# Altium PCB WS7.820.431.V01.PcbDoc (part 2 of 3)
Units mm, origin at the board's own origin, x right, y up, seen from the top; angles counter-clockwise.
Board outline 461 x 63.5 mm, 4 copper layers (Top Layer, Mid-Layer1, Mid-Layer 2, Bottom Layer); 379 components, 227 nets, 1092 pads, 3835 vias.
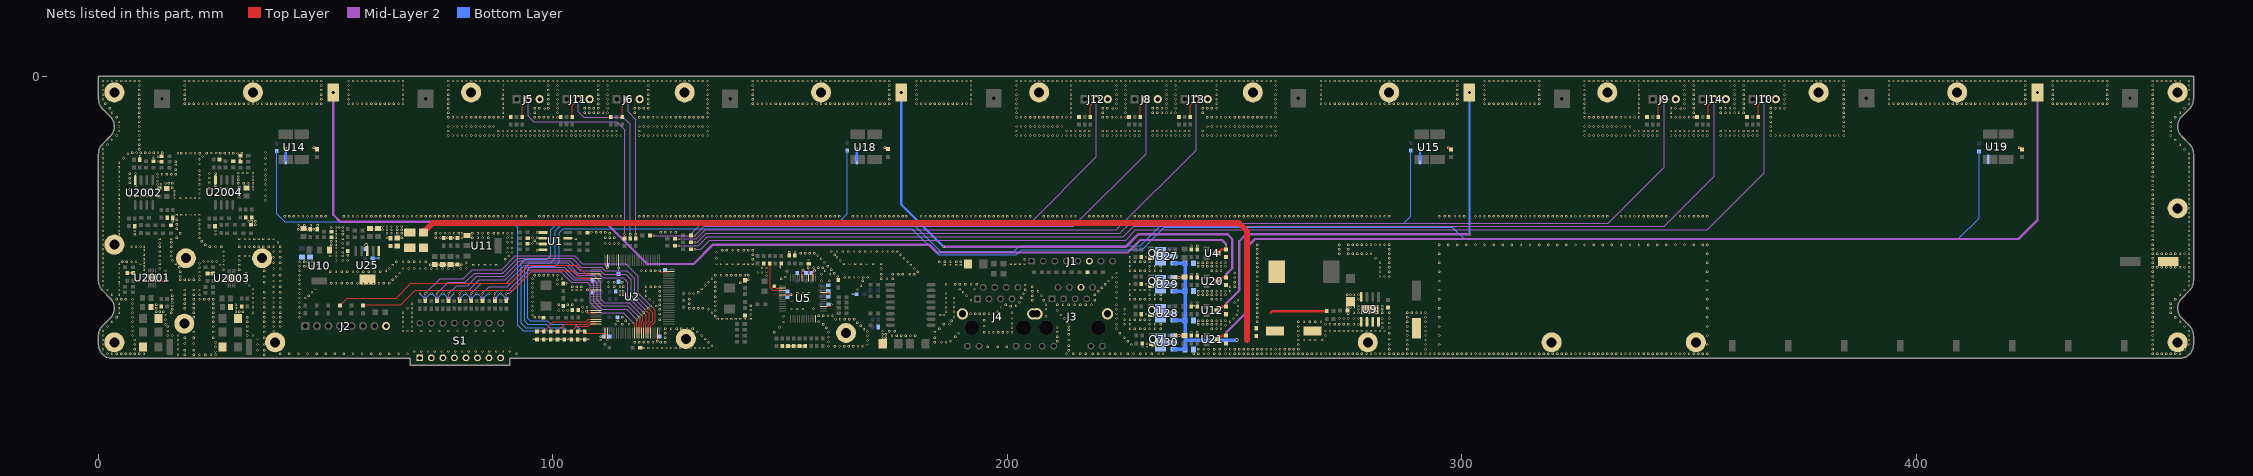
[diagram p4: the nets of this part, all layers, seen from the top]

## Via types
v1: diameter 0.508, hole 0.305, Top Layer to Bottom Layer, tented both sides, 3797 vias
v2: diameter 0.66, hole 0.406, Top Layer to Bottom Layer, tented both sides, 20 vias
v3: diameter 0.6, hole 0.305, Top Layer to Bottom Layer, tented both sides, 10 vias
v4: diameter 0.813, hole 0.508, Top Layer to Bottom Layer, tented both sides, 7 vias
v5: diameter 0.508, hole 0.3, Top Layer to Bottom Layer, tented both sides, 1 vias

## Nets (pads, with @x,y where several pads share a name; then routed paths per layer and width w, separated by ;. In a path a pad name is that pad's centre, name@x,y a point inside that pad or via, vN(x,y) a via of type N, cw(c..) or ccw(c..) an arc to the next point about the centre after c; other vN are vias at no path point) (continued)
+5V_13: FB16.2 R104.2 U29.1 | length 2.6
  Top Layer w0.381: R104.2@237.237,-44.209 R104.2@237.287,-44.159
  Top Layer w0.508: R104.2@237.287,-44.159 237.349,-44.221 237.721,-44.221 v2(237.75,-44.25) 237.779,-44.221 238.827,-44.221 FB16.2@238.888,-44.159
  Bottom Layer w0.508: U29.1@236.925,-44.159 236.995,-44.229 237.729,-44.229 v2(237.75,-44.25)
+5V_14: FB17.2 R105.2 U30.1 | length 2.9
  Top Layer w0.508: R105.2@237.244,-57.05 237.659,-57.05 237.709,-57 v2(237.75,-57) 237.761,-56.989 238.926,-56.989 FB17.2@238.937,-56.978
  Bottom Layer w0.508: U30.1@236.633,-57.035 236.65,-57.018 237.732,-57.018 v2(237.75,-57)
+5V_GS1: C142.2 TP17.1 U4.3 | length 235.3
  Top Layer w0.508: U4.3@246.238,-38.918 246.388,-38.918 246.634,-38.672 246.634,-38.522 247.088,-38.068 C142.2@248.104,-38.068 v1(248.104,-37.445)
  Mid-Layer 2 w0.508: TP17.1@51.662,-3.524 51.662,-30.412 53.25,-32 111.5,-32 120.75,-41.25 131,-41.25 135.25,-37 182.75,-37 184.5,-38.75 226.5,-38.75 229.25,-36 247.25,-36 248.104,-36.854 v1(248.104,-37.445)
+5V_GS2: C114.2 TP18.1 U20.3 | length 114.2
  Top Layer w0.508: U20.3@246.238,-45.05 246.388,-45.05 246.634,-44.804 246.634,-44.654 247.038,-44.25 C114.2@248.104,-44.25 ; C114.2@248.104,-44.2 v1(248.104,-43.577)
  Mid-Layer 2 w0.508: v1(186,-37.5) 226,-37.5 228.75,-34.75 248.5,-34.75 249.5,-35.75 249.5,-42.181 v1(248.104,-43.577)
  Bottom Layer w0.508: TP18.1@176.662,-3.524 176.662,-28.162 v1(186,-37.5)
+5V_GS3: C52.2 TP19.1 U12.3 | length 100.4
  Top Layer w0.508: U12.3@246.238,-51.465 246.388,-51.465 246.634,-51.219 246.634,-51.069 247.038,-50.665 C52.2@248.104,-50.665 ; C52.2@248.104,-50.615 v1(248.104,-49.992)
  Mid-Layer 2 w0.508: v1(248.104,-49.992) 251,-47.096 251,-36.251 252.501,-34.75 v1(301.662,-34.75)
  Bottom Layer w0.508: v1(301.662,-34.75) TP19.1@301.662,-3.524
+5V_GS4: C121.2 TP20.1 U21.3 | length 227.5
  Top Layer w0.508: U21.3@246.238,-57.878 246.388,-57.878 247.238,-57.028 C121.2@248.104,-57.028
  Mid-Layer 2 w0.508: v1(248.104,-56.405) 252.5,-52.009 252.5,-37.75 254.5,-35.75 422.5,-35.75 426.662,-31.588 TP20.1@426.662,-3.524
+6.9V: C12.2 C72.1 C132.2 C133.2 C134.2 C135.2 FB7.1 L4.2 R80.2 U27.3 U28.3 U29.3 U30.3 | length 259.9
  Top Layer w0.508: 257.92,-52.063 258.333,-51.65 R80.2@270.25,-51.65
  Top Layer w1.27: FB7.1@71.5,-34.3 71.6,-34.3 71.865,-34.035 71.865,-33.935 73.55,-32.25 250.965,-32.25 252.75,-34.035 252.75,-58
  Bottom Layer w0.762: U28.3@236.633,-53.622 236.649,-53.639 239.084,-53.639 C134.2@239.101,-53.655 ; U29.3@236.633,-47.207 236.649,-47.223 239.084,-47.223 C133.2@239.101,-47.24 ; U27.3@236.633,-41.075 236.649,-41.091 239.084,-41.091 C132.2@239.101,-41.108 C133.2@239.101,-47.24 ; U30.3@236.726,-59.942 U30.3@236.633,-60.035 236.665,-60.067 238.932,-60.067 239.08,-59.919 C135.2@239.08,-59.917 ; C135.2@239.055,-59.942 C135.2@239.08,-59.917 ; C135.2@239.207,-60.044 C135.2@239.08,-59.917 ; v4(250.5,-58) 239.101,-58 ; C135.2@239.08,-59.917 239.101,-59.896 239.101,-58 ; 239.101,-58 C134.2@239.101,-53.655 ; C134.2@239.101,-53.655 C133.2@239.101,-47.24
+6.9VIN: C128.2 C181.2 C183.2 FB7.2 R231.2 U25.1 | length 1.4
  Bottom Layer w0.381: R231.2@60.35,-40 v1(61.75,-40)
ACTLED: R45.2 U5.27 | length 8.3
  Top Layer w0.254: R45.2@147.782,-41.164 147.782,-46.472 148.376,-47.066 U5.27@150.529,-47.066
BD_TEMP1: J5.2 R24.2 R109.2 | length 54.6
  Top Layer w0.254: R24.2@93.25,-8.9 93.25,-6.29 J5.2@94.54,-5 ; R109.2@115.75,-35.65 v1(115.75,-34.75)
  Mid-Layer 2 w0.254: J5.2@94.54,-5 94.54,-8.79 95.75,-10 114.027,-10 115.75,-11.723 v1(115.75,-34.75)
BD_TEMP2: J11.2 R20.2 R110.2 | length 45
  Top Layer w0.254: R20.2@104.25,-8.9 104.25,-6.29 J11.2@105.54,-5 ; R110.2@117,-35.65 v1(117,-34.75)
  Mid-Layer 2 w0.254: J11.2@105.54,-5 105.54,-7.79 106.75,-9 115.5,-9 117,-10.5 v1(117,-34.75)
BD_TEMP3: J6.2 R21.2 R111.2 | length 35.8
  Top Layer w0.254: R21.2@115.25,-8.9 115.25,-6.29 J6.2@116.54,-5 ; R111.2@118.25,-35.65 v1(118.25,-34.75)
  Mid-Layer 2 w0.254: J6.2@116.54,-5 116.54,-7.79 118.25,-9.5 v1(118.25,-34.75)
BD_TEMP4: J12.2 R22.2 R112.2 | length 122.5
  Top Layer w0.254: R112.2@121.35,-35 v1(122.25,-35) ; R22.2@218.25,-8.9 218.25,-6.29 J12.2@219.54,-5
  Mid-Layer 2 w0.254: v1(122.25,-35) 130,-35 132.75,-32.25 205,-32.25 219.54,-17.71 J12.2@219.54,-5
BD_TEMP5: J8.2 R23.2 R113.2 | length 124.1
  Top Layer w0.254: R113.2@130.35,-35 v1(131.25,-35) ; R23.2@229.25,-8.9 229.25,-6.29 J8.2@230.54,-5
  Mid-Layer 2 w0.254: v1(131.25,-35) 133.25,-33 214.5,-33 230.54,-16.96 J8.2@230.54,-5
BD_TEMP6: J13.2 R62.2 R114.2 | length 138.4
  Top Layer w0.254: R114.2@126.85,-35.75 v1(127.75,-35.75) ; R62.2@240.25,-8.9 240.25,-6.29 J13.2@241.54,-5
  Mid-Layer 2 w0.254: v1(127.75,-35.75) 131.5,-35.75 133.5,-33.75 224,-33.75 241.54,-16.21 J13.2@241.54,-5
BD_TEMP7: J9.2 R70.2 R115.2 | length 240.4
  Top Layer w0.254: R115.2@130.35,-36.5 v1(131.25,-36.5) ; R70.2@343.25,-8.9 343.25,-6.29 J9.2@344.54,-5
  Mid-Layer 2 w0.254: v1(131.25,-36.5) 131.75,-36.5 133.75,-34.5 224.75,-34.5 227,-32.25 332.25,-32.25 344.54,-19.96 J9.2@344.54,-5
BD_TEMP8: J14.2 R79.2 R116.2 | length 256.4
  Top Layer w0.254: R116.2@126.85,-37.25 v1(127.75,-37.25) ; R79.2@354.25,-8.9 354.25,-6.29 J14.2@355.54,-5
  Mid-Layer 2 w0.254: v1(127.75,-37.25) 132,-37.25 134,-35.25 225.5,-35.25 227.75,-33 344.5,-33 355.54,-21.96 J14.2@355.54,-5
BD_TEMP9: J10.2 R81.2 R117.2 | length 263.8
  Top Layer w0.254: R117.2@130.35,-38 v1(131.25,-38) ; R81.2@365.25,-8.9 365.25,-6.29 J10.2@366.54,-5
  Mid-Layer 2 w0.254: v1(131.25,-38) 132.5,-38 134.5,-36 226,-36 228.25,-33.75 354,-33.75 366.54,-21.21 J10.2@366.54,-5
BOOT0: R10.2 U2.94 | length 3
  Top Layer w0.254: v1(114.468,-42.117) U2.94@114.468,-40.455
  Bottom Layer w0.254: R10.2@114.468,-43.438 v1(114.468,-42.117)
COMM_LED: R32.2 U2.5 | length 55.1
  Top Layer w0.254: R32.2@58.216,-50.404 58.37,-50.25 66.5,-50.25 69.75,-47 91.25,-47 95.5,-42.75 104.5,-42.75 106.205,-44.455 U2.5@109.468,-44.455
CURR_LED: R30.2 U2.3 | length 60.9
  Top Layer w0.254: R30.2@53.136,-50.404 53.136,-50.354 53.409,-50.081 53.459,-50.081 54.79,-48.75 65.5,-48.75 68.75,-45.5 90.75,-45.5 94.75,-41.5 105.252,-41.5 107.206,-43.455 U2.3@109.468,-43.455
DUPLED: TP1.1 U5.26 | length 2
  Top Layer w0.254: TP1.1@148.679,-46.149 149.096,-46.566 U5.26@150.529,-46.566
GND: C1.1 C2.1 C3.1 C4.1 C5.1 C6.1 C7.1 C8.1 C9.1 C10.2 C11.2 C12.1 C15.1 C18.2 C19.2 C22.1 C23.1 C24.1 C25.1 C26.1 C27.1 C28.1 C29.1 C30.1 C31.1 C32.1 C33.1 C34.1 C35.1 C36.1 C37.1 C38.1 C39.1 C40.1 C41.1 C42.1 C43.1 C52.1 C61.1 C64.2 C65.1 C66.1 C67.1 C68.1 C69.1 C70.1 C71.2 C72.2 C73.1 C74.1 C75.2 C76.1 C77.1 C78.1 C79.1 C80.1 C82.1 C83.1 C84.1 C85.1 C86.1 C87.2 C88.1 C89.1 C90.2 C91.2 C92.1 C93.1 C94.1 C95.1 C98.2 C99.2 C100.1 C101.1 C102.2 C103.1 C104.1 C105.1 C106.1 C107.2 C108.2 C109.2 C110.2 C114.1 C121.1 C128.1 C129.1 C132.1 C133.1 C134.1 C135.1 C141.1 C142.1 C181.1 C182.1 C183.1 C185.1 C2001.1 C2002.2 C2005.2 C2006.2 C2009.1 C2010.1 C2011.1 C2012.1 C2013.1 C2014.1 C2015.1 C2016.2 C2019.2 C2020.2 C2023.1 C2024.1 C2025.1 C2026.1 C2027.1 C2028.1 D1.1 D2.2 D3.2 D4.2 D5.2 D6.2 D7.2 D8.2 D9.2 J1.6 J2.8 J3.6 J3.13 J3.14 J4.13 J4.14 J5.3 J6.3 J8.3 J9.3 J10.3 J11.3 J12.3 J13.3 J14.3 pad.@3.5,-3.5 pad.@3.5,-37 pad.@3.5,-58.5 pad.@18.88,-54.4 pad.@19.25,-40 pad.@34,-3.5 pad.@36,-40 pad.@38.88,-58.5 pad.@82,-3.5 pad.@129,-3.5 pad.@129.25,-57.75 pad.@159,-3.5 pad.@164.5,-56.443 pad.@207,-3.5 pad.@254,-3.5 pad.@279.31,-58.5 pad.@284,-3.5 pad.@319.75,-58.5 pad.@332,-3.5 pad.@351.5,-58.5 pad.@378.5,-3.5 pad.@409,-3.5 pad.@457.5,-3.5 pad.@457.5,-29 pad.@457.5,-58.5 Q1.2 Q5.2 Q6.2 Q7.2 R8.1 R10.1 R15.1 R52.1 R55.1 R56.1 R57.1 R58.1 R59.1 R60.1 R82.2 R86.1 R103.1 R162.1 R165.1 R169.2 R184.1 R2002.2 R2009.1 R2010.1 R2011.1 R2016.1 R2018.1 R2021.1 R2027.1 R2031.1 R2032.1 R2033.1 R2037.1 S1.1 S1.2 S1.3 S1.4 S1.5 S1.6 S1.7 S1.8 U1.1 U1.2 U1.3 U1.4 U1.7 U2.10 U2.19 U2.20 U2.27 U2.49 U2.74 U2.99 U5.3 U5.9 U5.14 U5.16 U5.19 U5.29 U5.48 U9.4 U9.5 U9.6 U9.7 U9.8 U9.9 U10.1 U11.1 U14.4 U15.4 U18.4 U19.4 U25.3 U25.6 U27.2 U27.4 U28.2 U28.4 U29.2 U29.4 U30.2 U30.4 U2001.5 U2001.17 U2002.4 U2003.5 U2003.17 U2004.4 | length 62.5
  Top Layer w0.254: U2001.17@12.54,-45.09 U2001.5@13.39,-45.09 ; U2003.17@30.025,-45.15 U2003.5@30.875,-45.15 ; v1(107.583,-46.955) U2.10@109.468,-46.955 ; U2.20@109.468,-51.955 107.705,-51.955 v1(107.444,-51.693) 107.682,-51.455 U2.19@109.468,-51.455 ; U2.27@111.968,-56.455 111.968,-57.844 v1(112.013,-57.888) ; v1(111.968,-42.117) U2.99@111.968,-40.455 ; v1@122.968,-58.267 U2.49@122.968,-56.455 ; v1(123.5,-42.75) 123.569,-42.75 123.774,-42.955 U2.74@125.468,-42.955 ; U5.29@150.529,-48.066 152.35,-48.066 v3(152.362,-48.054) ; U5.19@154.779,-44.316 154.779,-42.97 v3(155.029,-42.72) ; U5.16@156.279,-44.316 156.279,-42.519 ; U5.14@157.279,-44.316 157.279,-43.137 157.696,-42.72 v3(157.569,-42.72) ; U5.3@159.529,-50.566 160.983,-50.566 161.303,-50.245 v1(161.303,-50.195) ; U5.9@159.529,-47.566 160.772,-47.566 v1(160.935,-47.729)
  Top Layer w0.305: U2001.5@13.39,-45.09 14.452,-45.09 14.537,-45.006
  Top Layer w0.508: C2001.1@6.33,-43.262 C2002.2@7.634,-43.262 ; C2015.1@23.992,-43.333 v1(24.697,-43.333) C2016.2@25.296,-43.333 ; v1(47.369,-15.716) 47.651,-15.716 C88.1@47.995,-16.06 ; v1(173.02,-15.716) 173.302,-15.716 C100.1@173.646,-16.06 ; v1(296.972,-15.716) 297.254,-15.716 C89.1@297.598,-16.06 ; v1(422.624,-15.716) 422.906,-15.716 C101.1@423.25,-16.06
  Bottom Layer w0.254: v1(70.75,-47.75) 70.75,-47.766 71.809,-48.825 D4.2@71.909,-48.825 72.009,-48.825 73.036,-47.799 73.201,-47.799 v1(73.25,-47.75) 73.299,-47.799 73.394,-47.799 74.42,-48.825 D2.2@74.52,-48.825 74.62,-48.825 75.695,-47.75 v1(75.75,-47.75) 75.799,-47.799 75.934,-47.799 76.96,-48.825 D3.2@77.06,-48.825 77.16,-48.825 78.235,-47.75 v1(78.25,-47.75) ; D6.2@79.461,-48.825 79.561,-48.825 80.587,-47.799 80.701,-47.799 v1(80.75,-47.75) 80.799,-47.799 80.875,-47.799 81.901,-48.825 D5.2@82.001,-48.825 82.101,-48.825 83.127,-47.799 83.201,-47.799 v1(83.25,-47.75) 83.3,-47.75 84.4,-48.85 D8.2@84.5,-48.85 84.6,-48.85 85.651,-47.799 85.951,-47.799 v1(86,-47.75) ; D9.2@87.25,-48.85 87.35,-48.85 88.45,-47.75 v1(88.5,-47.75) 88.55,-47.75 89.65,-48.85 D7.2@89.75,-48.85
  Bottom Layer w0.508: U14.4@41.183,-18.339 v1(41.183,-15.741) ; U18.4@166.834,-18.339 v1(166.834,-15.741) ; U15.4@290.786,-18.339 v1(290.786,-15.741)
  other v1: 17.5,-61.25 19,-61.25 21,-61.25 22.25,-61.25 23.5,-61.25 24.75,-61.25 25.75,-61.25 36.5,-61.25 2,-61 3,-61 4,-61 5,-61 6,-61 7,-61 8,-61 9,-61 10,-61 40,-61 42,-61 44,-61 46,-61 48,-61 50,-61 52,-61 54,-61 56,-61 58,-61 60,-61 62,-61 64,-61 66,-61 68,-61 92,-61 213,-61 214.5,-61 216,-61 217.25,-61 218.75,-61 220,-61 221.25,-61 222.5,-61 223.75,-61 225,-61 226.5,-61 227.75,-61 229.25,-61 230.5,-61 231.75,-61 233.25,-61 234.25,-61 241,-61 242,-61 243.25,-61 244.25,-61 245.5,-61 246.75,-61 248,-61 249,-61 250,-61 251,-61 252,-61 253,-61 254,-61 255,-61 256,-61 257,-61 258,-61 259,-61 260,-61 261,-61 262,-61 263,-61 264,-61 265,-61 266,-61 267,-61 268,-61 269,-61 269,-61 270,-61 271,-61 272,-61 273,-61 274,-61 275,-61 276,-61 277,-61 278,-61 279,-61 280,-61 281,-61 282,-61 283,-61 284,-61 285,-61 286,-61 287,-61 288,-61 289,-61 290,-61 291,-61 292,-61 293,-61 294,-61 295,-61 296,-61 297,-61 298,-61 299,-61 300,-61 301,-61 302,-61 303,-61 304,-61 305,-61 306,-61 307,-61 308,-61 309,-61 310,-61 311,-61 312,-61 313,-61 314,-61 315,-61 316,-61 317,-61 318,-61 319,-61 320,-61 321,-61 322,-61 323,-61 324,-61 325,-61 326,-61 327,-61 328,-61 329,-61 330,-61 331,-61 332,-61 333,-61 334,-61 335,-61 336,-61 337,-61 338,-61 339,-61 340,-61 341,-61 342,-61 343,-61 344,-61 345,-61 346,-61 347,-61 348,-61 349,-61 350,-61 351,-61 352,-61 353,-61 354,-61 354,-61 354,-61 452,-61 453,-61 454,-61 455,-61 456,-61 457,-61 458,-61 25.75,-60.5 69.5,-60.5 71,-60.5 72.5,-60.5 74,-60.5 75.5,-60.5 77,-60.5 78.5,-60.5 80,-60.5 81.5,-60.5 83,-60.5 84.5,-60.5 86,-60.5 87.5,-60.5 89,-60.5 90.5,-60.5 19,-60.25 21,-60.25 35,-60.25 36.5,-60.25 213.5,-60.25 1,-60 8,-60 17.5,-60 242,-60 243.25,-60 244.25,-60 245.5,-60 246.75,-60 248,-60 249,-60 250,-60 251,-60 252,-60 253,-60 254,-60 254,-60 255,-60 256,-60 257,-60 258,-60 259,-60 260,-60 261,-60 262,-60 263,-60 264,-60 284,-60 288,-60 292,-60 452,-60 459,-60 120,-59.75 121,-59.75 122,-59.75 123,-59.75 124,-59.75 125,-59.75 126,-59.75 127,-59.75 128,-59.75 130.25,-59.75 131.25,-59.75 132.25,-59.75 133.25,-59.75 134.25,-59.75 234.25,-59.75 229.726,-59.55 230.726,-59.55 231.945,-59.55 25.75,-59.5 233,-59.5 195.691,-59.484 197.85,-59.484 199.882,-59.484 162.04,-59.376 163.056,-59.376 164.072,-59.376 165.088,-59.376 166.104,-59.376 167.12,-59.376 168.136,-59.376 151.177,-59.357 152.447,-59.357 153.717,-59.357 154.987,-59.357 160.643,-59.364 135,-59.25 213.5,-59.25 169.227,-59.11 1,-59 8,-59 17.5,-59 35,-59 36.5,-59 227.25,-59 264,-59 284,-59 288,-59 292,-59 295,-59 354,-59 452,-59 460,-59 230.726,-58.8 19,-58.75 21,-58.75 25.75,-58.5 118,-58.5 119,-58.5 120,-58.5 121,-58.5 122,-58.5 123.75,-58.5 124.75,-58.5 134.25,-58.5 184,-58.5 185.5,-58.5 186.5,-58.5 160.643,-58.348 122.938,-58.297 187.5,-58.25 211,-58.25 226.5,-58.25 169.227,-58.094 1,-58 8,-58 17.5,-58 110.5,-58 213.5,-58 264,-58 265.25,-58 266.5,-58 267.75,-58 269.25,-58 269.25,-58 288,-58 292,-58 452,-58 460,-58 35,-57.75 95.75,-57.75 97.25,-57.75 98.75,-57.75 100.25,-57.75 101.75,-57.75 103.25,-57.75 104.75,-57.75 106.25,-57.75 107.75,-57.75 133.5,-57.75 284,-57.75 19,-57.5 21,-57.5 25.25,-57.5 36.5,-57.5 124.75,-57.5 172.5,-57.5 173.25,-57.5 184,-57.5 225.75,-57.5 160.643,-57.332 110.5,-57.25 188.5,-57.25 211,-57.25 169.227,-57.078 174.613,-57.078 175.629,-57.078 176.645,-57.078 177.661,-57.078 178.677,-57.078 179.693,-57.078 1,-57 7.5,-57 15.25,-57 16.25,-57 17.5,-57 32.75,-57 34,-57 132.75,-57 264,-57 270,-57 288,-57 292,-57 295,-57 354,-57 452,-57 460,-57 172.5,-56.75 173.25,-56.75 213.5,-56.75 124.75,-56.5 189.25,-56.5 224.75,-56.5 284,-56.5 148.705,-56.316 160.643,-56.316 194.929,-56.309 195.945,-56.309 196.961,-56.309 197.977,-56.309 198.993,-56.309 200.009,-56.309 201.025,-56.309 21,-56.25 25.25,-56.25 36.5,-56.25 131.75,-56.25 184,-56.25 211,-56.25 240.5,-56.25 241.75,-56.25 169.227,-56.062 173.978,-56.062 175.248,-56.062 1,-56 7.5,-56 15.25,-56 32.75,-56 38.5,-56 67,-56 68,-56 69,-56 71,-56 73,-56 75,-56 77,-56 79,-56 81,-56 83,-56 85,-56 87,-56 89,-56 172.5,-56 264,-56 270,-56 271,-56 272,-56 273,-56 274,-56 275,-56 276,-56 277,-56 278,-56 279,-56 280,-56 281,-56 282,-56 283,-56 288,-56 292,-56 452,-56 460,-56 213.5,-55.75 168.434,-55.598 124.75,-55.5 126,-55.5 127.25,-55.5 128.25,-55.5 129.5,-55.5 130.75,-55.5 185,-55.5 224,-55.5 227,-55.5 228,-55.5 229.25,-55.5 230.25,-55.5 231.25,-55.5 232.5,-55.5 233.75,-55.5 245,-55.5 246,-55.5 247,-55.5 160.135,-55.3 201.025,-55.293 211,-55.25 282.5,-55.25 284,-55.25 149.848,-55.173 2,-55 7.5,-55 15.25,-55 25.25,-55 32.75,-55 36.5,-55 38.5,-55 40,-55 67,-55 69,-55 213.5,-55 264,-55 288,-55 292,-55 295,-55 354,-55 452,-55 459,-55 194.929,-54.912 167.715,-54.879 248,-54.75 159.5,-54.538 14.75,-54.5 113.75,-54.5 115.25,-54.5 116.75,-54.5 186,-54.5 187.25,-54.5 224,-54.5 225.75,-54.5 227,-54.5 231.25,-54.5 232.5,-54.5 233.75,-54.5 242,-54.5 243,-54.5 244,-54.5 245,-54.5 246,-54.5 247,-54.5 270,-54.5 271,-54.5 272,-54.5 273,-54.5 274,-54.5 275,-54.5 276.25,-54.5 277.25,-54.5 201.025,-54.277 213.25,-54.25 282.5,-54.25 284,-54.25 166.997,-54.161 150.737,-54.03 3,-54 7.5,-54 25.25,-54 32.75,-54 36.5,-54 38.5,-54 40,-54 67,-54 69,-54 249,-54 255,-54 264,-54 265.25,-54 266.5,-54 267.75,-54 269,-54 288,-54 292,-54 452,-54 458,-54 158.484,-53.903 114.25,-53.75 116,-53.75 187.75,-53.75 242,-53.75 243,-53.75 244,-53.75 245,-53.75 246,-53.75 247,-53.75 248,-53.75 194.929,-53.642 14.75,-53.5 123.5,-53.5 225.75,-53.5 227,-53.5 228,-53.5 229.25,-53.5 230.25,-53.5 231.25,-53.5 166.278,-53.442 136.25,-53.384 137.25,-53.384 138.25,-53.384 139.25,-53.384 140.25,-53.384 141.25,-53.384 142.25,-53.384 143.5,-53.384 162.167,-53.395 163.183,-53.395 164.199,-53.395 165.215,-53.395 201.025,-53.261 212.5,-53.25 224,-53.25 249.75,-53.25 273,-53.25 274,-53.25 275,-53.25 276.25,-53.25 277.25,-53.25 282.5,-53.25 284,-53.25 4,-53 7.5,-53 21,-53 25.25,-53 32.75,-53 36.5,-53 38.5,-53 40,-53 44.25,-53 67,-53 69,-53 96,-53 97,-53 115.25,-53 188.25,-53 255,-53 288,-53 292,-53 295,-53 354,-53 452,-53 457,-53 135.75,-52.75 150.737,-52.76 208.5,-52.75 158.484,-52.668 159.5,-52.668 160.516,-52.668 161.532,-52.668 14.75,-52.5 95.5,-52.5 185.25,-52.5 186,-52.5 211.75,-52.5 250.5,-52.5 143.5,-52.384 123.5,-52.25 191.881,-52.245 192.897,-52.245 193.913,-52.245 194.929,-52.245 195.945,-52.245 196.961,-52.245 224,-52.25 225.75,-52.25 230.5,-52.25 275,-52.25 4.5,-52 7.5,-52 16,-52 21,-52 25.25,-52 34,-52 36.5,-52 38.5,-52 40,-52 44.25,-52 67,-52 69,-52 135,-52 201.025,-51.991 255,-52 276.25,-52 277.25,-52 278.25,-52 279.25,-52 280.25,-52 281.25,-52 282.5,-52 284,-52 288,-52 289,-52 290,-52 291,-52 292,-52 452,-52 456,-52 197.806,-51.781 12.75,-51.75 13.5,-51.75 14.25,-51.75 30.25,-51.75 31,-51.75 31.75,-51.75 106.5,-51.75 186.5,-51.75 188.25,-51.75 95.5,-51.5 101.25,-51.5 102.25,-51.5 103.25,-51.5 135.75,-51.5 211,-51.5 250.75,-51.5 143.5,-51.384 16.25,-51.25 123.5,-51.25 134.25,-51.25 208.5,-51.25 224,-51.25 225.75,-51.25 277.25,-51.25 278.25,-51.25 279.25,-51.25 280.25,-51.25 281.25,-51.25 282.5,-51.25 152.489,-51.165 153.759,-51.165 155.029,-51.165 157.341,-51.109 4.5,-51 7.5,-51 12.75,-51 19,-51 21,-51 25.25,-51 30.25,-51 68,-51 69,-51 130,-51 131,-51 132,-51 133,-51 255,-51 295,-51 354,-51 452,-51 452,-51 456,-51 198.612,-50.848 34,-50.75 36.5,-50.75 38.5,-50.75 40,-50.75 44.25,-50.75 106.5,-50.75 107.5,-50.75 186.5,-50.75 188.25,-50.75 274.75,-50.75 275.5,-50.75 276.25,-50.75 200.771,-50.594 240.989,-50.528 16.25,-50.5 95.5,-50.5 122.75,-50.5 135.75,-50.5 250.75,-50.5 277.25,-50.5 278.25,-50.5 278.25,-50.5 279.25,-50.5 280.25,-50.5 281.25,-50.5 282.5,-50.5 143.498,-50.474 201.914,-50.467 12.75,-50.25 30.25,-50.25 101.25,-50.25 103.25,-50.25 104.25,-50.25 123.5,-50.25 208.5,-50.25 211,-50.25 212.25,-50.25 213.5,-50.25 214.75,-50.25 216,-50.25 217.25,-50.25 218.5,-50.25 224,-50.25 199.628,-50.213 4.5,-50 7.5,-50 19,-50 21,-50 25.25,-50 69,-50 130,-50 255,-50 452,-50 456,-50 16.25,-49.75 34,-49.75 36.5,-49.75 38.5,-49.75 40,-49.75 44.25,-49.75 122,-49.75 186.5,-49.75 188.25,-49.75 240.5,-49.75 241.75,-49.75 250,-49.75 202.676,-49.705 95.5,-49.5 135.75,-49.5 152.489,-49.387 153.759,-49.387 155.029,-49.387 156.299,-49.387 123.5,-49.25 192,-49.25 205.5,-49.25 208,-49.25 219.25,-49.25 250.75,-49.25 4,-49 5,-49 6,-49 7.5,-49 16.25,-49 19,-49 21,-49 22.25,-49 23.25,-49 24.25,-49 25.25,-49 121.25,-49 130,-49 227,-49 228,-49 229.25,-49 230.25,-49 231.25,-49 232.5,-49 233.75,-49 245,-49 246,-49 247,-49 255,-49 277.25,-49 295,-49 354,-49 452,-49 457,-49 34,-48.75 36.5,-48.75 38.5,-48.75 40,-48.75 44.25,-48.75 45.5,-48.75 186.5,-48.75 188.25,-48.75 224,-48.75 203.057,-48.689 95.5,-48.5 135.75,-48.5 16.25,-48.25 46.25,-48.25 120.5,-48.25 123.5,-48.25 191,-48.25 205.5,-48.25 207.5,-48.25 3,-48 4.5,-48 19,-48 21,-48 22.25,-48 114.75,-48 115.5,-48 219.25,-48 227,-48 231.25,-48 232.5,-48 233.75,-48 242,-48 243,-48 244,-48 245,-48 246,-48 247,-48 248,-48 255,-48 274.75,-48 275.5,-48 276.25,-48 277.25,-48 452,-48 458,-48 165.994,-47.851 203.565,-47.8 34,-47.75 44.25,-47.75 130,-47.75 131,-47.75 186.5,-47.75 153.759,-47.736 155.029,-47.736 156.299,-47.736 36.5,-47.5 38.5,-47.5 40,-47.5 47,-47.5 95.5,-47.5 132,-47.5 190.25,-47.5 224,-47.5 114.75,-47.25 115.5,-47.25 120.5,-47.25 123.5,-47.25 135.75,-47.25 205.5,-47.25 206.75,-47.25 220,-47.25 242,-47.25 243,-47.25 244,-47.25 245,-47.25 246,-47.25 247,-47.25 248,-47.25 249,-47.25 2,-47 4.5,-47 16,-47 19,-47 21,-47 22.25,-47 104.25,-47 105.25,-47 106.25,-47 227,-47 228,-47 229.25,-47 230.25,-47 231.25,-47 255,-47 295,-47 354,-47 452,-47 459,-47 167.01,-46.962 203.946,-46.911 34,-46.75 44.25,-46.75 47.75,-46.75 132.75,-46.75 189.5,-46.75 192.75,-46.75 95.5,-46.5 220.75,-46.5 38.5,-46.25 40,-46.25 104.25,-46.25 105.25,-46.25 106.25,-46.25 112.25,-46.25 113.5,-46.25 114.75,-46.25 115.5,-46.25 120.5,-46.25 121.5,-46.25 122.5,-46.25 123.5,-46.25 135.75,-46.25 205.5,-46.25 224,-46.25 249,-46.25 250,-46.25 167.772,-46.073 1,-46 4.5,-46 33.25,-46 133.5,-46 255,-46 460,-46 451.885,-45.957 203.946,-45.895 44.25,-45.75 101,-45.75 186.5,-45.75 188.5,-45.75 189.5,-45.75 190.75,-45.75 192,-45.75 193.25,-45.75 221.5,-45.75 227,-45.75 230.5,-45.75 51.25,-45.5 52.25,-45.5 53.5,-45.5 54.75,-45.5 55.75,-45.5 57,-45.5 58.25,-45.5 59.5,-45.5 60.5,-45.5 61.75,-45.5 62.75,-45.5 64,-45.5 95.5,-45.5 103,-45.5 141.25,-45.384 4.5,-45.25 32.5,-45.25 36.5,-45.25 112.25,-45.25 113.5,-45.25 115.25,-45.25 134.25,-45.25 135.75,-45.25 224,-45.25 250,-45.25 1,-45 38.5,-45 40,-45 222.25,-45 255,-45 295,-45 354,-45 452,-45 460,-45 159.093,-44.942 160.871,-44.942 168.153,-44.93 11.308,-44.874 12.07,-44.874 28.843,-44.806 29.605,-44.806 14.75,-44.75 18,-44.75 19,-44.75 20,-44.75 21,-44.75 22.25,-44.75 44.25,-44.75 64.75,-44.75 101,-44.75 143,-44.75 95.5,-44.5 102,-44.5 135,-44.5 150.229,-44.505 172.25,-44.5 173.5,-44.5 174.75,-44.5 4.5,-44.25 32.5,-44.25 164.199,-44.251 165.215,-44.251 166.231,-44.251 167.247,-44.251 168.263,-44.251 169.279,-44.251 223,-44.25 224,-44.25 250,-44.25 151.118,-44.124 28.843,-44.044 29.605,-44.044 1,-44 18,-44 36.5,-44 65.5,-44 162.649,-43.996 255,-44 282,-44 283,-44 284,-44 452,-44 460,-44 22.225,-43.963 147,-43.884 11.308,-43.858 12.07,-43.858 14.75,-43.75 38.5,-43.75 40,-43.75 44.25,-43.75 96,-43.75 97,-43.75 98,-43.75 99,-43.75 100,-43.75 101,-43.75 135.75,-43.75 137,-43.75 138.25,-43.75 139.25,-43.75 140.25,-43.75 141.25,-43.75 142.25,-43.75 143,-43.75 159.093,-43.545 160.949,-43.499 172.25,-43.5 174.75,-43.5 176,-43.5 177,-43.5 178.5,-43.5 179.5,-43.5 240.5,-43.5 241.75,-43.5 161.931,-43.277 4.5,-43.25 6.981,-43.248 32.5,-43.25 66.25,-43.25 224,-43.25 250,-43.25 145,-43.134 146,-43.134 22.225,-43.018 1,-43 18,-43 51,-43 52.25,-43 53.5,-43 54.75,-43 56,-43 57,-43 58.25,-43 59.5,-43 60.75,-43 62,-43 147.003,-43.006 180.25,-43 255,-43 282,-43 284,-43 295,-43 354,-43 452,-43 460,-42.952 14.75,-42.75 36.5,-42.75 44.25,-42.75 63.25,-42.75 119.5,-42.75 120.5,-42.75 121.5,-42.75 122.5,-42.75 227,-42.75 228,-42.75 229.25,-42.75 230.25,-42.75 231.25,-42.75 232.5,-42.75 233.75,-42.75 245,-42.75 246,-42.75 247,-42.75 159.881,-42.727 161.212,-42.559 10,-42.5 27.5,-42.5 31,-42.5 4.5,-42.25 13.5,-42.25 38.5,-42.25 40,-42.25 64,-42.25 67,-42.25 68.25,-42.25 69.5,-42.25 70.75,-42.25 72,-42.25 73.25,-42.25 74.5,-42.25 75.75,-42.25 77,-42.25 78.25,-42.25 79.75,-42.25 81,-42.25 172.25,-42.25 179.5,-42.25 146,-42.134 147,-42.134 156.198,-42.092 157.341,-42.092 158.357,-42.092 159.373,-42.092 22.225,-42.073 1,-42 17.75,-42 255,-42 282,-42 284,-42 452,-42 453,-42 454,-42 455,-42 456,-42 457,-42 458,-42 459,-42 460,-42 149.949,-41.958 10,-41.75 44.25,-41.75 45.25,-41.75 46,-41.75 47,-41.75 160.5,-41.75 227,-41.75 231.25,-41.75 232.5,-41.75 233.75,-41.75 242,-41.75 243,-41.75 244,-41.75 245,-41.75 246,-41.75 247,-41.75 248,-41.75 26.75,-41.5 27.5,-41.5 31,-41.5 64.75,-41.5 82.5,-41.5 83.75,-41.5 85,-41.5 86.25,-41.5 87.5,-41.5 178.75,-41.5 186.25,-41.5 187.5,-41.5 188.75,-41.5 189.75,-41.5 73,-41.4 74.9,-41.4 76.6,-41.4 78.3,-41.4 79.8,-41.4 4.5,-41.25 9.25,-41.25 13.5,-41.25 17,-41.25 48.25,-41.25 136,-41.25 137,-41.25 138.25,-41.25 139.5,-41.25 140.75,-41.25 142,-41.25 143,-41.25 144,-41.25 164,-41.25 165.25,-41.25 166.5,-41.25 167.75,-41.25 169,-41.25 170.5,-41.25 172.25,-41.25 200.75,-41.25 201.75,-41.25 202.75,-41.25 203.75,-41.25 22.225,-41.128 1,-41 10,-41 38.5,-41 40,-41 81,-41 242,-41 243,-41 244,-41 245,-41 246,-41 247,-41 248,-41 255,-41 282,-41 284,-41 295,-41 354,-41 452,-41 460,-41 159.75,-40.884 5.25,-40.75 6.25,-40.75 7.25,-40.75 8.25,-40.75 44.25,-40.75 45.25,-40.75 46,-40.75 47,-40.75 65.5,-40.75 67,-40.75 68.25,-40.75 69.5,-40.75 70.75,-40.75 72,-40.75 178,-40.75 185,-40.75 186.25,-40.75 187.5,-40.75 188.75,-40.75 189.75,-40.75 227,-40.75 228,-40.75 229.25,-40.75 230.25,-40.75 231.25,-40.75 23.17,-40.717 24.115,-40.717 25.059,-40.717 26.004,-40.717 13.5,-40.5 16.25,-40.5 27.5,-40.5 31,-40.5 52.25,-40.5 53.75,-40.5 54.886,-40.5 163.25,-40.5 156.25,-40.384 10,-40.25 89.5,-40.25 144,-40.25 203.75,-40.25 159,-40.134 1,-40 136,-40 177.25,-40 255,-40 281,-40 284,-40 452,-40 460,-40 38.5,-39.75 40,-39.75 162.5,-39.75 227,-39.75 230.5,-39.75 13.5,-39.5 16,-39.5 27.5,-39.5 31,-39.5 32.25,-39.5 33.25,-39.5 51,-39.5 52.25,-39.5 53.75,-39.5 90.25,-39.5 158.25,-39.384 54.886,-39.366 10,-39.25 144,-39.25 162,-39.25 176.5,-39.25 1,-39 255,-39 273,-39 275,-39 276,-39 277,-39 278,-39 279,-39 280,-39 284,-39 295,-39 354,-39 452,-39 453,-39 454,-39 455,-39 457,-39 458,-39 459,-39 460,-39 154.5,-38.884 155.5,-38.884 156.5,-38.884 157.5,-38.884 52.25,-38.75 53.75,-38.75 90,-38.75 91,-38.75 136,-38.75 152.007,-38.665 153.277,-38.665 13.5,-38.5 16,-38.5 27.5,-38.5 38.5,-38.5 40,-38.5 161.25,-38.5 162.5,-38.5 163.75,-38.5 165,-38.5 166.25,-38.5 167.5,-38.5 168.75,-38.5 170,-38.5 171.25,-38.5 172.5,-38.5 173.75,-38.5 174.75,-38.5 175.75,-38.5 10,-38.25 96.5,-38.25 137.25,-38.25 138.25,-38.25 139.5,-38.25 140.75,-38.25 142,-38.25 143,-38.25 144,-38.25 1,-38 255,-38 273,-38 275,-38 284,-38 452,-38 460,-38 52.25,-37.75 53.75,-37.75 90,-37.75 91,-37.75 7.25,-37.5 8.25,-37.5 9.25,-37.5 10,-37.5 13.5,-37.5 16,-37.5 24.5,-37.5 25.75,-37.5 27,-37.5 31,-37.5 32.25,-37.5 33.25,-37.5 34.25,-37.5 35.25,-37.5 36.25,-37.5 37.5,-37.5 38.5,-37.5 40,-37.5 240.5,-37.25 241.75,-37.25 1,-37 23.5,-37 51.25,-37 52.25,-37 255,-37 273,-37 275,-37 276,-37 277,-37 278,-37 279,-37 280,-37 281,-37 282,-37 283,-37 284,-37 295,-37 297,-37 299,-37 301,-37 303,-37 305,-37 307,-37 309,-37 311,-37 313,-37 315,-37 317,-37 319,-37 321,-37 323,-37 325,-37 327,-37 329,-37 331,-37 333,-37 335,-37 337,-37 339,-37 341,-37 343,-37 345,-37 347,-37 349,-37 351,-37 353,-37 354,-37 354,-37 452,-37 460,-37 13.5,-36.75 53.75,-36.75 95.5,-36.75 96.5,-36.75 111.5,-36.75 112.5,-36.75 113.5,-36.75 114.5,-36.75 16,-36.5 39.5,-36.5 90,-36.5 91,-36.5 22.75,-36.25 51.25,-36.25 52.25,-36.25 96,-36.125 1,-36 452,-36 460,-36 13.5,-35.75 16,-35.75 31,-35.75 32.25,-35.75 33.25,-35.75 34.25,-35.75 35.25,-35.75 36.25,-35.75 37.5,-35.75 38.5,-35.75 53.75,-35.75 105,-35.75 17.25,-35.5 22.25,-35.5 52.25,-35.5 63.5,-35.5 66.75,-35.5 74.25,-35.5 75.25,-35.5 76.75,-35.5 78.25,-35.5 80,-35.5 82.25,-35.5 83.5,-35.5 84.5,-35.5 85.75,-35.5 90,-35.5 91,-35.5 95.5,-35.5 96.5,-35.5 111.5,-35.5 112.5,-35.5 113.5,-35.5 1,-35 452,-35 460,-35 4.5,-34.75 8,-34.75 25.75,-34.75 52.25,-34.75 53.75,-34.75 18,-34.5 22.25,-34.5 63.5,-34.5 64.5,-34.5 65.75,-34.5 66.75,-34.5 74.25,-34.5 75.25,-34.5 76.25,-34.5 77.25,-34.5 78.25,-34.5 79.25,-34.5 80,-34.5 82.25,-34.5 83.5,-34.5 84.5,-34.5 85.75,-34.5 87,-34.5 88,-34.5 89,-34.5 90,-34.5 91,-34.5 112.5,-34.5 96.5,-34.25 108.5,-34.25 109.5,-34.25 110.5,-34.25 111.5,-34.25 123.75,-34.25 124.75,-34.25 126,-34.25 127,-34.25 1,-34 4.5,-34 8,-34 25.75,-34 52.25,-34 53.75,-34 452,-34 452,-34 460,-34 62.5,-33.75 63.5,-33.75 64.5,-33.75 65.75,-33.75 66.75,-33.75 60.601,-33.686 43.988,-33.651 46.003,-33.628 47.4,-33.614 17.25,-33.5 22.25,-33.5 51.25,-33.25 52.25,-33.25 53,-33.25 53.75,-33.25 1,-33 4.5,-33 62.5,-33 63.5,-33 64.5,-33 65.75,-33 66.75,-33 452,-33 460,-33 44,-32.75 45.25,-32.75 46.75,-32.75 48.25,-32.75 34.5,-32.65 17.25,-32.5 22.25,-32.5 1,-32 4.5,-32 452,-32 460,-32 16.38,-31.877 33,-31.85 33.75,-31.85 34.5,-31.85 17.25,-31.5 22.25,-31.5 1,-31 4.5,-31 452,-31 460,-31 41,-30.75 42,-30.75 43,-30.75 44,-30.75 45,-30.75 46,-30.75 47,-30.75 48,-30.75 49,-30.75 50,-30.75 54,-30.75 55,-30.75 56,-30.75 57,-30.75 58,-30.75 59,-30.75 60,-30.75 61,-30.75 62,-30.75 63,-30.75 64,-30.75 65,-30.75 66,-30.75 67,-30.75 68,-30.75 69,-30.75 70,-30.75 71,-30.75 72,-30.75 73,-30.75 74,-30.75 75,-30.75 76,-30.75 77,-30.75 78,-30.75 79,-30.75 80,-30.75 81,-30.75 82,-30.75 83,-30.75 84,-30.75 85,-30.75 86,-30.75 87,-30.75 88,-30.75 89,-30.75 90,-30.75 91,-30.75 92,-30.75 93,-30.75 94,-30.75 97,-30.75 98,-30.75 99,-30.75 100,-30.75 101,-30.75 102,-30.75 103,-30.75 104,-30.75 105,-30.75 106,-30.75 107,-30.75 108,-30.75 109,-30.75 110,-30.75 111,-30.75 112,-30.75 113,-30.75 114,-30.75 115,-30.75 119,-30.75 120,-30.75 121,-30.75 122,-30.75 123,-30.75 124,-30.75 125,-30.75 126,-30.75 127,-30.75 128,-30.75 129,-30.75 130,-30.75 131,-30.75 132,-30.75 133,-30.75 134,-30.75 135,-30.75 136,-30.75 137,-30.75 138,-30.75 139,-30.75 140,-30.75 141,-30.75 142,-30.75 143,-30.75 144,-30.75 145,-30.75 146,-30.75 147,-30.75 148,-30.75 149,-30.75 150,-30.75 151,-30.75 152,-30.75 153,-30.75 154,-30.75 155,-30.75 156,-30.75 157,-30.75 158,-30.75 159,-30.75 160,-30.75 161,-30.75 162,-30.75 163,-30.75 166,-30.75 167,-30.75 168,-30.75 169,-30.75 170,-30.75 171,-30.75 172,-30.75 173,-30.75 174,-30.75 175,-30.75 176,-30.75 177,-30.75 177.75,-30.75 181,-30.75 182,-30.75 183,-30.75 184,-30.75 185,-30.75 186,-30.75 187,-30.75 188,-30.75 189,-30.75 190,-30.75 191,-30.75 192,-30.75 193,-30.75 194,-30.75 195,-30.75 196,-30.75 197,-30.75 198,-30.75 199,-30.75 200,-30.75 201,-30.75 202,-30.75 203,-30.75 204,-30.75 205,-30.75 208,-30.75 209,-30.75 210,-30.75 211,-30.75 212,-30.75 213,-30.75 214,-30.75 215,-30.75 218,-30.75 219,-30.75 220,-30.75 221,-30.75 222,-30.75 223,-30.75 224,-30.75 225,-30.75 228,-30.75 229,-30.75 230,-30.75 231,-30.75 232,-30.75 233,-30.75 234,-30.75 235,-30.75 236,-30.75 237,-30.75 238,-30.75 239,-30.75 240,-30.75 241,-30.75 242,-30.75 243,-30.75 244,-30.75 245,-30.75 246,-30.75 247,-30.75 248,-30.75 249,-30.75 250,-30.75 251,-30.75 252,-30.75 253,-30.75 254,-30.75 255,-30.75 256,-30.75 257,-30.75 258,-30.75 259,-30.75 260,-30.75 261,-30.75 262,-30.75 263,-30.75 264,-30.75 265,-30.75 266,-30.75 267,-30.75 268,-30.75 269,-30.75 270,-30.75 271,-30.75 272,-30.75 273,-30.75 274,-30.75 275,-30.75 276,-30.75 277,-30.75 278,-30.75 279,-30.75 280,-30.75 281,-30.75 282,-30.75 283,-30.75 284,-30.75 295,-30.75 296.25,-30.75 297.25,-30.75 298.5,-30.75 299.5,-30.75 300.5,-30.75 303,-30.75 304,-30.75 305,-30.75 306,-30.75 307,-30.75 308,-30.75 309,-30.75 310,-30.75 311,-30.75 312,-30.75 313,-30.75 314,-30.75 315,-30.75 316,-30.75 317,-30.75 318,-30.75 319,-30.75 320,-30.75 321,-30.75 322,-30.75 323,-30.75 324,-30.75 325,-30.75 326,-30.75 327,-30.75 328,-30.75 329,-30.75 330,-30.75 331,-30.75 332,-30.75 335,-30.75 336,-30.75 337,-30.75 338,-30.75 339,-30.75 340,-30.75 341,-30.75 342,-30.75 343,-30.75 344,-30.75 345,-30.75 348,-30.75 349,-30.75 350,-30.75 351,-30.75 352,-30.75 353,-30.75 354,-30.75 17.25,-30.5 18.25,-30.5 19.25,-30.5 20.25,-30.5 21.25,-30.5 22.25,-30.5 1,-30 4.5,-30 452,-30 460,-30 1,-29 4.5,-29 452,-29 460,-29 1,-28 4.5,-28 452,-28 460,-28 36.75,-27.25 1,-27 4.5,-27 452,-27 460,-27 16.75,-26.75 18,-26.75 19.25,-26.75 20.25,-26.75 21.25,-26.75 22.25,-26.75 6.88,-26.377 8.13,-26.377 9.38,-26.377 10.63,-26.377 11.63,-26.377 36.75,-26.25 24.405,-26.1 25.655,-26.1 26.905,-26.1 28.155,-26.1 29.405,-26.1 1,-26 4.5,-26 16.75,-26 452,-26 460,-26 22.25,-25.75 16.75,-25.25 1,-25 4.5,-25 34,-25 36.75,-25 452,-25 460,-25 11.821,-24.915 6.88,-24.877 9.38,-24.877 10.63,-24.877 22.25,-24.75 24.405,-24.6 26.905,-24.6 28.155,-24.6 29.405,-24.6 16.25,-24.5 34,-24.25 25.732,-24.072 8.146,-24.051 1,-24 4.5,-24 452,-24 460,-24 13,-23.75 13.75,-23.75 22.25,-23.75 36.75,-23.75 14.75,-23.5 15.5,-23.5 16.25,-23.5 30.75,-23.5 32,-23.5 33,-23.5 34,-23.5 6.88,-23.377 24.405,-23.35 1,-23 4.5,-23 13,-23 452,-23 460,-23 22.25,-22.75 30.75,-22.75 34,-22.75 36.75,-22.75 6.88,-22.377 24.405,-22.35 13,-22.25 1,-22 4.5,-22 30.75,-22 34,-22 452,-22 460,-22 22.25,-21.75 36.75,-21.75 13,-21.5 14,-21.5 15,-21.5 16,-21.5 17,-21.5 25.783,-21.408 6.88,-21.377 8.138,-21.359 24.405,-21.35 30.75,-21.25 31.75,-21.25 32.75,-21.25 34,-21.25 1,-21 4.5,-21 452,-21 460,-21 22.25,-20.75 17,-20.5 36.75,-20.5 1,-20 4.5,-20 452,-20 460,-20 17,-19.5 22.25,-19.25 36.75,-19.25 1,-19 4.5,-19 452,-19 460,-19 17,-18.75 13.091,-18.692 22.25,-18.25 31.117,-18.144 1,-18 5.5,-18 36.75,-18 452,-18 460,-18 12.13,-17.877 13.091,-17.676 22.905,-17.6 9.154,-17.549 1,-17 6.5,-17 452,-17 460,-17 17.5,-16.891 18.25,-16.891 19.25,-16.891 20.25,-16.891 21.25,-16.891 22.312,-16.891 23.802,-16.891 26.819,-16.895 27.764,-16.895 28.709,-16.895 29.654,-16.895 30.598,-16.895 31.543,-16.895 24.818,-16.85 25.905,-16.85 7.437,-16.787 8.382,-16.787 9.327,-16.787 10.271,-16.787 11.216,-16.787 12.161,-16.787 13.106,-16.787 14.051,-16.787 36.75,-16.75 1,-16 9,-16 452,-16 459,-16 415.848,-15.651 2,-15 9,-15 452,-15 458,-15 3,-14 9,-14 452,-14 457,-14 4,-13 9,-13 77,-13 78,-13 79,-13 80,-13 81,-13 82,-13 83,-13 84,-13 85,-13 86,-13 87,-13 88,-13 89,-13 90,-13 91,-13 92,-13 93,-13 94,-13 95,-13 96,-13 97,-13 98,-13 99,-13 100,-13 101,-13 102,-13 103,-13 104,-13 105,-13 106,-13 107,-13 108,-13 109,-13 109,-13 110,-13 111,-13 112,-13 113,-13 114,-13 115,-13 119,-13 120,-13 121,-13 122,-13 123,-13 124,-13 125,-13 126,-13 127,-13 128,-13 129,-13 130,-13 131,-13 132,-13 133,-13 134,-13 202,-13 203,-13 204,-13 205,-13 206,-13 207,-13 208,-13 209,-13 210,-13 211,-13 212,-13 213,-13 214,-13 215,-13 216,-13 217,-13 218,-13 221,-13 222,-13 223,-13 224,-13 225,-13 226,-13 227,-13 228,-13 229,-13 232,-13 233,-13 234,-13 234,-13 235,-13 236,-13 237,-13 238,-13 239,-13 240,-13 243,-13 244,-13 245,-13 246,-13 247,-13 248,-13 249,-13 250,-13 251,-13 252,-13 253,-13 254,-13 255,-13 256,-13 257,-13 258,-13 259,-13 327,-13 328,-13 329,-13 330,-13 331,-13 332,-13 333,-13 334,-13 335,-13 336,-13 337,-13 338,-13 339,-13 340,-13 341,-13 342,-13 343,-13 346,-13 347,-13 348,-13 349,-13 350,-13 351,-13 352,-13 353,-13 354,-13 357,-13 358,-13 359,-13 359,-13 360,-13 361,-13 362,-13 363,-13 364,-13 365,-13 368,-13 369,-13 370,-13 371,-13 372,-13 373,-13 374,-13 375,-13 376,-13 377,-13 378,-13 379,-13 380,-13 381,-13 382,-13 383,-13 384,-13 452,-13 456,-13 4.5,-12 9,-12 77,-12 88,-12 89,-12 90,-12 91,-12 92,-12 93,-12 94,-12 95,-12 96,-12 97,-12 98,-12 99,-12 100,-12 101,-12 102,-12 103,-12 104,-12 105,-12 106,-12 107,-12 108,-12 109,-12 110,-12 111,-12 112,-12 113,-12 114,-12 119,-12 134,-12 202,-12 213,-12 214,-12 215,-12 216,-12 217,-12 218,-12 221,-12 222,-12 223,-12 224,-12 225,-12 226,-12 227,-12 228,-12 229,-12 232,-12 233,-12 234,-12 235,-12 236,-12 237,-12 238,-12 239,-12 240,-12 243,-12 259,-12 327,-12 338,-12 339,-12 340,-12 341,-12 342,-12 343,-12 346,-12 347,-12 348,-12 349,-12 350,-12 351,-12 352,-12 353,-12 354,-12 357,-12 358,-12 359,-12 360,-12 361,-12 362,-12 363,-12 364,-12 365,-12 368,-12 384,-12 452,-12 456,-12 4.5,-11 9,-11 77,-11 78,-11 79,-11 80,-11 81,-11 82,-11 83,-11 84,-11 85,-11 86,-11 87,-11 119,-11 120,-11 121,-11 122,-11 123,-11 124,-11 125,-11 126,-11 127,-11 128,-11 129,-11 130,-11 131,-11 132,-11 133,-11 134,-11 202,-11 203,-11 204,-11 205,-11 206,-11 207,-11 208,-11 209,-11 210,-11 211,-11 212,-11 244,-11 245,-11 246,-11 247,-11 248,-11 249,-11 250,-11 251,-11 252,-11 253,-11 254,-11 255,-11 256,-11 257,-11 258,-11 259,-11 327,-11 328,-11 329,-11 330,-11 331,-11 332,-11 333,-11 334,-11 335,-11 336,-11 337,-11 368,-11 384,-11 452,-11 456,-11 4.5,-10 9,-10 368,-10 384,-10 452,-10 456,-10 4,-9 9,-9 77,-9 78,-9 79,-9 80,-9 81,-9 82,-9 83,-9 84,-9 85,-9 86,-9 87,-9 88,-9 89,-9 96,-9 97,-9 98,-9 99,-9 100,-9 101,-9 119,-9 120,-9 121,-9 122,-9 122,-9 123,-9 124,-9 125,-9 126,-9 127,-9 128,-9 129,-9 130,-9 131,-9 131,-9 132,-9 133,-9 134,-9 134,-9 202,-9 202,-9 203,-9 203,-9 204,-9 204,-9 205,-9 205,-9 206,-9 206,-9 207,-9 207,-9 208,-9 208,-9 209,-9 209,-9 210,-9 210,-9 211,-9 211,-9 212,-9 212,-9 213,-9 213,-9 214,-9 214,-9 221,-9 221,-9 222,-9 222,-9 223,-9 223,-9 224,-9 224,-9 225,-9 225,-9 226,-9 226,-9 244,-9 244,-9 245,-9 245,-9 246,-9 246,-9 247,-9 247,-9 247,-9 247,-9 248,-9 248,-9 249,-9 249,-9 250,-9 250,-9 251,-9 251,-9 252,-9 252,-9 253,-9 253,-9 254,-9 254,-9 255,-9 255,-9 256,-9 256,-9 256,-9 256,-9 257,-9 257,-9 258,-9 258,-9 259,-9 259,-9 259,-9 259,-9 327,-9 328,-9 329,-9 330,-9 331,-9 332,-9 333,-9 334,-9 335,-9 336,-9 337,-9 338,-9 339,-9 346,-9 347,-9 348,-9 349,-9 350,-9 351,-9 368,-9 384,-9 384,-9 452,-9 457,-9 3,-8 9,-8 77,-8 89,-8 96,-8 101,-8 107,-8 108,-8 109,-8 110,-8 111,-8 112,-8 118,-8 134,-8 202,-8 202,-8 214,-8 214,-8 221,-8 221,-8 226,-8 226,-8 232,-8 232,-8 233,-8 233,-8 234,-8 234,-8 235,-8 235,-8 236,-8 236,-8 237,-8 237,-8 243,-8 243,-8 259,-8 259,-8 327,-8 339,-8 346,-8 351,-8 357,-8 358,-8 359,-8 360,-8 361,-8 362,-8 368,-8 384,-8 452,-8 458,-8 98.172,-7.032 223.172,-7.032 223.172,-7.032 348.172,-7.032 2.5,-7 9,-7 77,-7 89,-7 96,-7 97,-7 99,-7 101,-7 107,-7 107,-7 108,-7 109,-7 110,-7 112,-7 118,-7 119,-7 120,-7 121,-7 134,-7 202,-7 202,-7 214,-7 214,-7 221,-7 221,-7 222,-7 222,-7 224,-7 224,-7 226,-7 226,-7 232,-7 232,-7 232,-7 232,-7 233,-7 233,-7 234,-7 234,-7 235,-7 235,-7 237,-7 237,-7 243,-7 243,-7 244,-7 244,-7 245,-7 245,-7 246,-7 246,-7 259,-7 259,-7 327,-7 339,-7 346,-7 347,-7 349,-7 351,-7 357,-7 357,-7 358,-7 359,-7 360,-7 362,-7 368,-7 369,-7 370,-7 371,-7 384,-7 452,-7 459,-7 1.5,-6 9,-6 19,-6 20,-6 21,-6 22,-6 23,-6 24,-6 25,-6 26,-6 27,-6 28,-6 29,-6 30,-6 31,-6 32,-6 33,-6 34,-6 35,-6 36,-6 37,-6 38,-6 39,-6 40,-6 41,-6 42,-6 43,-6 44,-6 45,-6 46,-6 47,-6 48,-6 49,-6 49,-6 55,-6 55,-6 56,-6 57,-6 58,-6 59,-6 60,-6 61,-6 62,-6 63,-6 64,-6 65,-6 66,-6 67,-6 77,-6 89,-6 99,-6 101,-6 110,-6 112,-6 121,-6 134,-6 144,-6 144,-6 145,-6 145,-6 146,-6 146,-6 147,-6 147,-6 148,-6 148,-6 149,-6 149,-6 150,-6 150,-6 151,-6 151,-6 152,-6 152,-6 153,-6 153,-6 154,-6 154,-6 155,-6 155,-6 156,-6 156,-6 157,-6 157,-6 158,-6 158,-6 159,-6 159,-6 160,-6 160,-6 161,-6 161,-6 162,-6 162,-6 163,-6 163,-6 164,-6 164,-6 165,-6 165,-6 166,-6 166,-6 167,-6 167,-6 168,-6 168,-6 169,-6 169,-6 170,-6 170,-6 171,-6 171,-6 172,-6 172,-6 173,-6 173,-6 174,-6 174,-6 180,-6 180,-6 181,-6 181,-6 182,-6 182,-6 183,-6 183,-6 184,-6 184,-6 185,-6 185,-6 186,-6 186,-6 187,-6 187,-6 188,-6 188,-6 189,-6 189,-6 190,-6 190,-6 191,-6 191,-6 192,-6 192,-6 202,-6 202,-6 214,-6 214,-6 224,-6 224,-6 226,-6 226,-6 235,-6 235,-6 237,-6 237,-6 246,-6 246,-6 259,-6 259,-6 269,-6 270,-6 271,-6 272,-6 273,-6 274,-6 275,-6 276,-6 277,-6 278,-6 279,-6 280,-6 281,-6 282,-6 283,-6 284,-6 285,-6 286,-6 287,-6 288,-6 289,-6 290,-6 291,-6 292,-6 293,-6 294,-6 295,-6 296,-6 297,-6 298,-6 299,-6 305,-6 306,-6 307,-6 308,-6 309,-6 310,-6 311,-6 312,-6 313,-6 314,-6 315,-6 316,-6 317,-6 327,-6 339,-6 349,-6 351,-6 360,-6 362,-6 371,-6 384,-6 394,-6 395,-6 396,-6 397,-6 398,-6 399,-6 400,-6 401,-6 402,-6 403,-6 404,-6 405,-6 406,-6 407,-6 408,-6 409,-6 410,-6 411,-6 412,-6 413,-6 414,-6 415,-6 416,-6 417,-6 418,-6 419,-6 420,-6 421,-6 422,-6 423,-6 424,-6 430,-6 431,-6 432,-6 433,-6 434,-6 435,-6 436,-6 437,-6 438,-6 439,-6 440,-6 441,-6 442,-6 452,-6 460,-6 1,-5 9,-5 19,-5 49,-5 55,-5 67,-5 67,-5 77,-5 99,-5 101,-5 110,-5 112,-5 121,-5 134,-5 144,-5 144,-5 174,-5 174,-5 180,-5 180,-5 192,-5 192,-5 192,-5 192,-5 202,-5 202,-5 224,-5 224,-5 226,-5 226,-5 235,-5 235,-5 237,-5 237,-5 246,-5 246,-5 259,-5 259,-5 269,-5 299,-5 305,-5 317,-5 317,-5 327,-5 349,-5 351,-5 360,-5 362,-5 371,-5 384,-5 394,-5 424,-5 430,-5 442,-5 442,-5 452,-5 460,-5 88.99,-4.901 213.99,-4.901 213.99,-4.901 338.99,-4.901 1,-4 9,-4 19,-4 49,-4 55,-4 67,-4 77,-4 89,-4 99,-4 101,-4 110,-4 112,-4 121,-4 134,-4 144,-4 144,-4 174,-4 174,-4 180,-4 180,-4 192,-4 192,-4 202,-4 202,-4 214,-4 214,-4 224,-4 224,-4 226,-4 226,-4 235,-4 235,-4 237,-4 237,-4 246,-4 246,-4 259,-4 259,-4 269,-4 299,-4 305,-4 317,-4 327,-4 339,-4 349,-4 351,-4 360,-4 362,-4 371,-4 384,-4 394,-4 424,-4 430,-4 442,-4 452,-4 1,-3 9,-3 19,-3 49,-3 55,-3 67,-3 77,-3 89,-3 99,-3 101,-3 110,-3 112,-3 121,-3 134,-3 144,-3 144,-3 174,-3 174,-3 180,-3 180,-3 192,-3 192,-3 202,-3 202,-3 214,-3 214,-3 224,-3 224,-3 226,-3 226,-3 235,-3 235,-3 237,-3 237,-3 246,-3 246,-3 259,-3 259,-3 269,-3 299,-3 305,-3 317,-3 327,-3 339,-3 349,-3 351,-3 360,-3 362,-3 371,-3 384,-3 394,-3 424,-3 430,-3 442,-3 452,-3 460,-3 1,-2 9,-2 19,-2 49,-2 55,-2 67,-2 77,-2 89,-2 99,-2 101,-2 110,-2 112,-2 121,-2 134,-2 144,-2 144,-2 174,-2 174,-2 180,-2 180,-2 192,-2 192,-2 202,-2 202,-2 214,-2 214,-2 224,-2 224,-2 226,-2 226,-2 235,-2 235,-2 237,-2 237,-2 246,-2 246,-2 259,-2 259,-2 269,-2 299,-2 305,-2 317,-2 327,-2 339,-2 349,-2 351,-2 360,-2 362,-2 371,-2 384,-2 394,-2 424,-2 430,-2 442,-2 452,-2 460,-2 1,-1 2,-1 3,-1 4,-1 5,-1 6,-1 7,-1 8,-1 9,-1 19,-1 20,-1 21,-1 22,-1 23,-1 24,-1 25,-1 26,-1 27,-1 28,-1 29,-1 30,-1 30,-1 31,-1 32,-1 33,-1 34,-1 35,-1 36,-1 37,-1 38,-1 39,-1 40,-1 41,-1 42,-1 43,-1 44,-1 45,-1 46,-1 47,-1 48,-1 49,-1 55,-1 56,-1 57,-1 58,-1 59,-1 60,-1 61,-1 62,-1 63,-1 64,-1 65,-1 66,-1 67,-1 77,-1 78,-1 79,-1 80,-1 81,-1 82,-1 83,-1 83,-1 84,-1 85,-1 86,-1 87,-1 88,-1 89,-1 90,-1 91,-1 92,-1 93,-1 94,-1 95,-1 96,-1 97,-1 98,-1 99,-1 100,-1 101,-1 102,-1 103,-1 104,-1 104,-1 105,-1 106,-1 107,-1 108,-1 109,-1 110,-1 111,-1 112,-1 113,-1 114,-1 114,-1 114,-1 115,-1 116,-1 117,-1 118,-1 119,-1 120,-1 120,-1 121,-1 122,-1 123,-1 124,-1 124,-1 125,-1 126,-1 127,-1 128,-1 129,-1 130,-1 131,-1 132,-1 133,-1 134,-1 144,-1 144,-1 145,-1 145,-1 146,-1 146,-1 147,-1 147,-1 148,-1 148,-1 149,-1 149,-1 150,-1 150,-1 151,-1 151,-1 152,-1 152,-1 153,-1 153,-1 154,-1 154,-1 155,-1 155,-1 155,-1 155,-1 156,-1 156,-1 157,-1 157,-1 158,-1 158,-1 159,-1 159,-1 160,-1 160,-1 161,-1 161,-1 162,-1 162,-1 163,-1 163,-1 164,-1 164,-1 165,-1 165,-1 166,-1 166,-1 167,-1 167,-1 168,-1 168,-1 169,-1 169,-1 170,-1 170,-1 171,-1 171,-1 172,-1 172,-1 173,-1 173,-1 174,-1 174,-1 180,-1 180,-1 181,-1 181,-1 182,-1 182,-1 183,-1 183,-1 184,-1 184,-1 185,-1 185,-1 186,-1 186,-1 187,-1 187,-1 188,-1 188,-1 189,-1 189,-1 190,-1 190,-1 191,-1 191,-1 192,-1 192,-1 202,-1 202,-1 203,-1 203,-1 204,-1 204,-1 205,-1 205,-1 206,-1 206,-1 207,-1 207,-1 208,-1 208,-1 208,-1 208,-1 209,-1 209,-1 210,-1 210,-1 211,-1 211,-1 212,-1 212,-1 213,-1 213,-1 214,-1 214,-1 215,-1 215,-1 216,-1 216,-1 217,-1 217,-1 218,-1 218,-1 219,-1 219,-1 220,-1 220,-1 221,-1 221,-1 222,-1 222,-1 223,-1 223,-1 224,-1 224,-1 225,-1 225,-1 226,-1 226,-1 227,-1 227,-1 228,-1 228,-1 229,-1 229,-1 229,-1 229,-1 230,-1 230,-1 231,-1 231,-1 232,-1 232,-1 233,-1 233,-1 234,-1 234,-1 235,-1 235,-1 236,-1 236,-1 237,-1 237,-1 238,-1 238,-1 239,-1 239,-1 239,-1 239,-1 239,-1 239,-1 240,-1 240,-1 241,-1 241,-1 242,-1 242,-1 243,-1 243,-1 244,-1 244,-1 245,-1 245,-1 245,-1 245,-1 246,-1 246,-1 247,-1 247,-1 248,-1 248,-1 249,-1 249,-1 249,-1 249,-1 250,-1 250,-1 251,-1 251,-1 252,-1 252,-1 253,-1 253,-1 254,-1 254,-1 255,-1 255,-1 256,-1 256,-1 257,-1 257,-1 258,-1 258,-1 259,-1 259,-1 269,-1 270,-1 271,-1 272,-1 273,-1 274,-1 275,-1 276,-1 277,-1 278,-1 279,-1 280,-1 280,-1 281,-1 282,-1 283,-1 284,-1 285,-1 286,-1 287,-1 288,-1 289,-1 290,-1 291,-1 292,-1 293,-1 294,-1 295,-1 296,-1 297,-1 298,-1 299,-1 305,-1 306,-1 307,-1 308,-1 309,-1 310,-1 311,-1 312,-1 313,-1 314,-1 315,-1 316,-1 317,-1 327,-1 328,-1 329,-1 330,-1 331,-1 332,-1 333,-1 333,-1 334,-1 335,-1 336,-1 337,-1 338,-1 339,-1 340,-1 341,-1 342,-1 343,-1 344,-1 345,-1 346,-1 347,-1 348,-1 349,-1 350,-1 351,-1 352,-1 353,-1 354,-1 354,-1 355,-1 356,-1 357,-1 358,-1 359,-1 360,-1 361,-1 362,-1 363,-1 364,-1 364,-1 364,-1 365,-1 366,-1 367,-1 368,-1 369,-1 370,-1 370,-1 371,-1 372,-1 373,-1 374,-1 374,-1 375,-1 376,-1 377,-1 378,-1 379,-1 380,-1 381,-1 382,-1 383,-1 384,-1 394,-1 395,-1 396,-1 397,-1 398,-1 399,-1 400,-1 401,-1 402,-1 403,-1 404,-1 405,-1 405,-1 406,-1 407,-1 408,-1 409,-1 410,-1 411,-1 412,-1 413,-1 414,-1 415,-1 416,-1 417,-1 418,-1 419,-1 420,-1 421,-1 422,-1 423,-1 424,-1 430,-1 431,-1 432,-1 433,-1 434,-1 435,-1 436,-1 437,-1 438,-1 439,-1 440,-1 441,-1 442,-1 452,-1 453,-1 453,-1 454,-1 455,-1 456,-1 457,-1 458,-1 460,-1
  other v4: 58.95,-37.08
  other v5: 456,-39
I_SENSOR1: C92.2 C93.2 R93.2 U2.23 | length 109.4
  Top Layer w0.254: C92.2@96.5,-56.15 96.65,-56 97.85,-56 C93.2@98,-56.15 ; C93.2@97.95,-56.15 100.1,-54 107.25,-54 107.795,-53.455 U2.23@109.468,-53.455
  Bottom Layer w0.254: R93.2@39.191,-16.439 39.191,-30.191 41,-32 91,-32 92.25,-33.25 92.25,-54.75 93.5,-56 v1(97.25,-56)
I_SENSOR2: C103.2 C104.2 R100.2 U2.24 | length 125.6
  Top Layer w0.254: C103.2@99.5,-56.15 99.65,-56 v1(100.25,-56) 100.85,-56 C104.2@101,-56.15 ; C104.2@101.1,-56 102.6,-54.5 107.5,-54.5 108.045,-53.955 U2.24@109.468,-53.955
  Bottom Layer w0.254: v1(100.25,-56) 98.75,-56 98,-55.25 94,-55.25 93,-54.25 93,-41 93.75,-40.25 98.75,-40.25 99.5,-39.5 99.5,-33.75 101.25,-32 163,-32 164.75,-30.25 164.75,-16.364 R100.2@164.802,-16.312
I_SENSOR3: C94.2 C95.2 R94.2 U2.25 | length 252.3
  Top Layer w0.254: C94.2@102.5,-56.15 102.65,-56 v1(103.25,-56) 103.85,-56 C95.2@104,-56.15 104,-56.1 104.273,-55.827 104.323,-55.827 105.15,-55 107.75,-55 108.295,-54.455 U2.25@109.468,-54.455
  Bottom Layer w0.254: v1(103.25,-56) 102.5,-55.25 99.25,-55.25 98.5,-54.5 94.5,-54.5 93.75,-53.75 93.75,-42.111 94.861,-41 99.495,-41 100.5,-39.995 100.5,-34 101.75,-32.75 179.5,-32.75 185.25,-38.5 201.5,-38.5 202.77,-37.23 229.27,-37.23 234.2,-32.3 287.221,-32.3 288.754,-30.767 R94.2@288.754,-16.312
I_SENSOR4: C105.2 C106.2 R101.2 U2.26 | length 379
  Top Layer w0.254: C105.2@105.5,-56.15 105.65,-56 v1(106.25,-56) 106.85,-56 C106.2@107,-56.15 ; C106.2@107.152,-56.455 U2.26@111.468,-56.455
  Bottom Layer w0.254: v1(106.25,-56) 104.75,-54.5 99.5,-54.5 98.75,-53.75 95,-53.75 94.5,-53.25 94.5,-42.5 95.25,-41.75 100.5,-41.75 101.364,-40.886 101.364,-34.386 102.25,-33.5 179,-33.5 184.75,-39.25 202,-39.25 203.144,-38.106 229.644,-38.106 232,-35.75 234.566,-33.184 297.908,-33.184 300.474,-35.75 409.242,-35.75 413.804,-31.188 R101.2@413.804,-16.489
IO1: R177.2 U2.46 | length 68.2
  Top Layer w0.254: R177.2@71.912,-49.404 v1(71.912,-47.75) ; U2.46@121.468,-56.455 121.468,-55.032 122.5,-54 122.5,-51.5 v1(121.5,-50.5)
  Mid-Layer 2 w0.254: v1(71.912,-47.75) 75.162,-44.5 80.25,-44.5 82.25,-42.5 88.75,-42.5 91.75,-39.5 104.75,-39.5 106.5,-41.25 116,-41.25 118.75,-44 118.75,-47.75 v1(121.5,-50.5)
IO2: R27.2 U2.45 | length 64.3
  Top Layer w0.254: R27.2@74.495,-49.404 v1(74.495,-47.75) ; U2.45@120.968,-56.455 120.968,-54.782 122,-53.75 122,-52 v1(121,-51)
  Mid-Layer 2 w0.254: v1(74.495,-47.75) 76.989,-45.255 80.745,-45.255 82.75,-43.25 89,-43.25 92.25,-40 104.25,-40 106.25,-42 110.75,-42 111.5,-42.75 116.25,-42.75 118,-44.5 118,-48 v1(121,-51)
IO3: R25.2 U2.44 | length 60.5
  Top Layer w0.254: R25.2@77.035,-49.543 R25.2@77.035,-49.404 v1(77.035,-47.75) ; U2.44@120.468,-56.455 120.468,-54.532 121.25,-53.75 121.25,-52.25 v1(120.5,-51.5)
  Mid-Layer 2 w0.254: v1(77.035,-47.75) 78.785,-46 81.25,-46 83.25,-44 89.25,-44 92.75,-40.5 103.75,-40.5 106,-42.75 110.5,-42.75 111.25,-43.5 116,-43.5 117.25,-44.75 117.25,-48.25 v1(120.5,-51.5)
IO4: R118.2 U2.43 | length 56.3
  Top Layer w0.254: R118.2@79.5,-49.4 v1(79.5,-47.75) ; U2.43@119.968,-56.455 119.968,-54.282 120.5,-53.75 120.5,-52.5 v1(120,-52)
  Mid-Layer 2 w0.254: v1(79.5,-47.75) 80.25,-47 81.5,-47 83.75,-44.75 89.5,-44.75 93.25,-41 103.25,-41 105.5,-43.25 110,-43.25 110.988,-44.238 115.488,-44.238 116.5,-45.25 116.5,-48.5 v1(120,-52)
IO5: R120.2 U2.42 | length 52.7
  Top Layer w0.254: R120.2@82,-49.4 v1(82,-47.75) ; U2.42@119.468,-56.455 119.468,-54.032 119.75,-53.75 119.75,-52.819 119.5,-52.569 v1(119.5,-52.5)
  Mid-Layer 2 w0.254: v1(82,-47.75) 84.25,-45.5 89.75,-45.5 93.75,-41.5 103,-41.5 105.25,-43.75 109,-43.75 110.5,-45.25 110.5,-49 111.25,-49.75 116.75,-49.75 v1(119.5,-52.5)
IO6: R132.2 U2.41 | length 49
  Top Layer w0.254: R132.2@84.5,-49.4 v1(84.5,-47.75) ; U2.41@118.968,-56.455 118.968,-53.921 119.25,-53.639 119.25,-53.276 119,-53.026 v1(119,-53)
  Mid-Layer 2 w0.254: v1(84.5,-47.75) 86,-46.25 90,-46.25 94.25,-42 102.5,-42 104.75,-44.25 108.5,-44.25 109.75,-45.5 109.75,-49.25 111,-50.5 116.5,-50.5 118.125,-52.125 v1(119,-53)
IO7: R9.2 U2.40 | length 44.8
  Top Layer w0.254: R9.2@87.25,-49.4 v1(87.25,-47.75) ; U2.40@118.468,-56.455 118.484,-56.439 118.484,-53.516 v1(118.5,-53.5)
  Mid-Layer 2 w0.254: v1(87.25,-47.75) 88,-47 90.25,-47 94.75,-42.5 102.25,-42.5 104.5,-44.75 108,-44.75 109,-45.75 109,-49.5 110.75,-51.25 116.25,-51.25 v1(118.5,-53.5)
IO8: R14.2 U2.39 | length 40.8
  Top Layer w0.254: R14.2@89.75,-49.4 v1(89.75,-47.75) ; v1(117.75,-54.25) 117.75,-54.319 117.968,-54.537 U2.39@117.968,-56.455
  Mid-Layer 2 w0.254: v1(89.75,-47.75) 90.5,-47.75 95.25,-43 101.75,-43 104,-45.25 107.5,-45.25 108.25,-46 108.25,-49.75 110.5,-52 115.5,-52 v1(117.75,-54.25)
